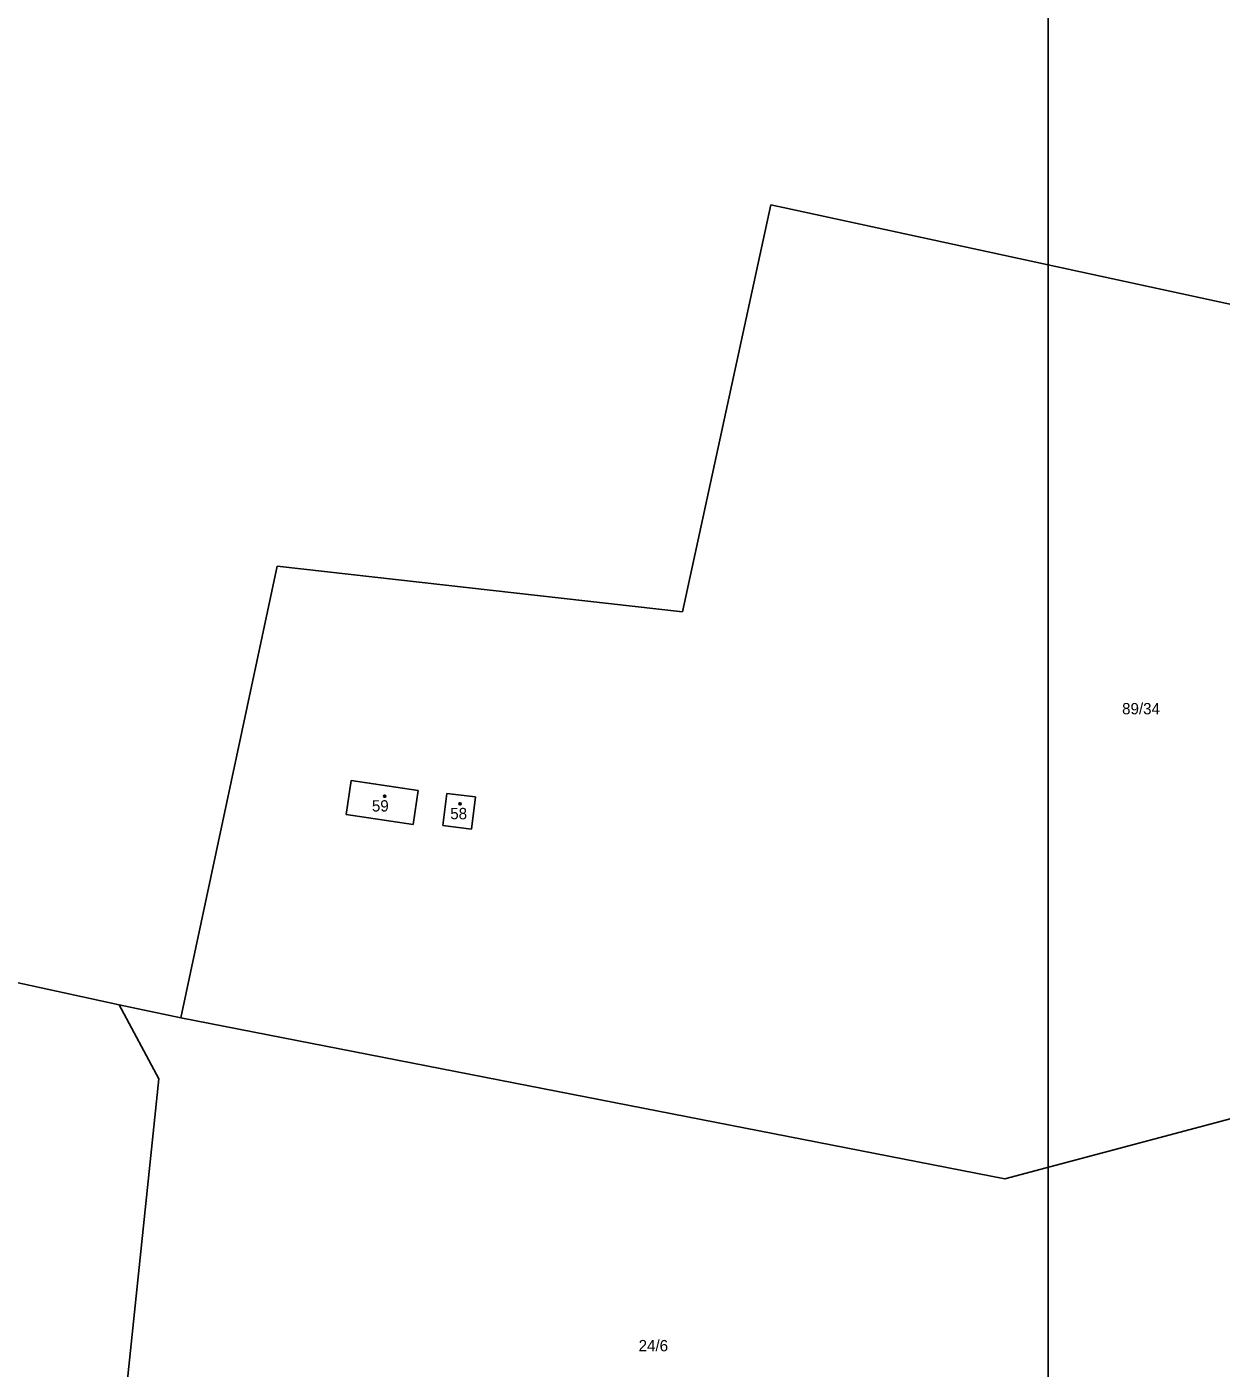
# Model space of a CAD drawing. Extents: x -752500 to -750336, y -1035826 to -1033500.
# Drawn here: x -751403.4 to -751224, y -1034303.4 to -1034101.8 of the extents above; entities that cross this region are included whole.
import ezdxf

# ---------------------------------------------------------------- set-up
doc = ezdxf.new("R2010")
doc.units = 0
for name, color, linetype in [('Default', 7, 'Continuous'), ('Hranice parcel', 7, 'Continuous'), ('ML1000', 7, 'Continuous'), ('Parcelní čísla', 7, 'Continuous'), ('Značky budov', 7, 'Continuous'), ('Značky kultur', 7, 'Continuous')]:
    doc.layers.add(name, color=color, linetype=linetype)

# ---------------------------------------------------------------- blocks, each defined once
blk = doc.blocks.new('NAHRADNI_SYMBOL')
at = {"layer": 'Default'}
blk.add_lwpolyline([(0.09, 0.15), (0.18, 0), (0.09, -0.15), (-0.09, -0.15), (-0.18, 0), (-0.09, 0.15), (0.09, 0.15)], dxfattribs=at)
blk = doc.blocks.new('402')
at = {"layer": 'Default'}
blk.add_lwpolyline([(0.09, 0.15), (0.18, 0), (0.09, -0.15), (-0.09, -0.15), (-0.18, 0), (-0.09, 0.15), (0.09, 0.15)], dxfattribs=at)

msp = doc.modelspace()

# ---------------------------------------------------------------- linework, layer by layer
at = {"layer": 'Hranice parcel'}
for p, q in [((-751291.67, -1034128.59), (-751304.92, -1034189.73)), ((-751218.12, -1034144.47), (-751291.67, -1034128.59)), ((-751365.81, -1034182.88), (-751380.27, -1034250.73)), ((-751304.92, -1034189.73), (-751365.81, -1034182.88)), ((-751354.68, -1034215.08), (-751355.44, -1034220.15)), ((-751344.64, -1034216.57), (-751354.68, -1034215.08)), ((-751345.39, -1034221.65), (-751344.64, -1034216.57)), ((-751340.3, -1034217), (-751340.9, -1034221.84)), ((-751336.02, -1034217.53), (-751340.3, -1034217)), ((-751336.62, -1034222.38), (-751336.02, -1034217.53)), ((-751355.44, -1034220.15), (-751345.39, -1034221.65)), ((-751340.9, -1034221.84), (-751336.62, -1034222.38)), ((-751391.16, -1034248.44), (-751416.41, -1034242.88)), ((-751389.53, -1034248.78), (-751391.16, -1034248.44)), ((-751389.53, -1034248.78), (-751383.59, -1034259.87)), ((-751380.27, -1034250.73), (-751389.53, -1034248.78)), ((-751256.5, -1034274.89), (-751380.27, -1034250.73)), ((-751179.17, -1034254.29), (-751256.5, -1034274.89)), ((-751383.59, -1034259.87), (-751389.73, -1034318.97))]:
    msp.add_line(p, q, dxfattribs=at)
at = {"layer": 'ML1000'}
msp.add_lwpolyline([(-751250, -1035000), (-751250, -1034500), (-751250, -1034000), (-751250, -1033500)], dxfattribs=at)

# ---------------------------------------------------------------- block references
at = {"layer": 'Značky budov'}
msp.add_blockref('402', (-751338.34, -1034218.55), dxfattribs=at)
at = {"layer": 'Značky kultur'}
msp.add_blockref('NAHRADNI_SYMBOL', (-751349.66, -1034217.42), dxfattribs=at)

# ---------------------------------------------------------------- texts
at = {"layer": 'Parcelní čísla'}
for s, p in [('89/34', (-751238.9, -1034205.12)), ('59', (-751351.58, -1034219.72)), ('58', (-751339.81, -1034220.88)), ('24/6', (-751311.52, -1034300.83))]:
    msp.add_text(s, height=1.7, dxfattribs=at).set_placement(p)

doc.saveas('drawing.dxf')
